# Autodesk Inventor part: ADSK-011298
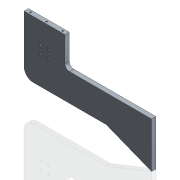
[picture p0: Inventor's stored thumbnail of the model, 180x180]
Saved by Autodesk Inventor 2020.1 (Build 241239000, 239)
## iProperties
Created: 1999-12
Part Number: ADSK-011298
Material: Pearson Aluminium
Document SubType Name: Modeling
Designer: sspink
Density: 2.71 g/cm^3
Appearance: Pearson-Aluminum
Mass: 1295.46 g
Surface Area: 939.34 cm^2
Volume: 478.029 cm^3
Control State: 0
Checked Out: False
Master: False
Shininess: 35.0
Length Units: 11269
Angle Units: 11279
Time Units: 11290
Mass Units: 11283
Length Display Precision: 3
Angle Display Precision: 2
Compacted: True
CUTLENGTH: 8.25 X 14.00 (116 SI)
MATERIAL DESC: SHEET,ALUM,0.50
MATERIAL_NUMBER: A101291
Dimensions: 356x210x12 mm
Mass: 1,295 kg
DocNumber: ADSK-011298.ipt
Folder: 01 - Themengebiete\Simplification\01 - Packaging machine\
VDS_Category: 3D Komponenten
Density: 2.71
Volumn: 499.8190191039328
Area: 951.0588557024685
PropertySet Name: Model Information
Author: sspink
Revision Number: -
Title: plate
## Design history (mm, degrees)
node "Solide1"
  node "Extrusion1" dims "d4" = 12, "d5" = 0
  node "Hole1" dims "d10" = 3.4, "d11" = 6.5, "d12" = 3.4, "d13" = 60 deg, "d14" = 19.05, "d15" = 118 deg, "d46" = 6
  node "Hole2" dims "d22" = 4.134, "d23" = 6.35, "d24" = 5.55625, "d25" = 60 deg, "d26" = 14.2, "d27" = 118 deg, "d48" = 10
sketch "Sketch1"
  geometry: L1 (-356, 210)-(-242, 210); L2 (-242, 210)-(-242, 139.5); L3 (-229.5, 127)-(0, 127); L4 (0, 127)-(0, 0); L5 (0, 0)-(-127, 50); L6 (-127, 50)-(-331, 50); L7 (-356, 75)-(-356, 210); L8 (-310, 151)-(-288, 151); L9 (-288, 151)-(-288, 129); L10 (-288, 129)-(-310, 129); L11 (-310, 129)-(-310, 151); A1 r 25 centre (-331, 75) between (-356, 75) and (-331, 50); A2 r 12.5 centre (-229.5, 139.5) between (-242, 139.5) and (-229.5, 127); 5 further points
  constraints: 22 end point, 5 perpendicular, 4 point on circle, 4 point on line, 4 tangent, 3 parallel, 2 centre point, 2 horizontal, 2 midpoint, 1 coincident, 1 vertical alignment
  dimensions: "d33" = 114 distance of L1.start L1.end; "d34" = 160 distance of point (-356, 50) L1.start; "d35" = 242 distance of point (-242, 127) L3.end; "d36" = 127 distance of L3.end L4.end; "d37" = 127 horizontal distance of L4.end L5.end; "d38" = 50 vertical distance of L4.end L5.end; "d39" = 25 radius of A1; "d40" = 12.5 radius of A2; "d43" = 22 distance of L8.start L8.end; "d44" = 22 distance of L8.end L9.end (= d43); "d45" = 59 distance from line of L1 L8.end
sketch "Sketch2"
  geometry: 4 further points
sketch "Sketch3"
  geometry: L1 (11.6, -6)-(101.6, -6); L2 (-0.4, 0)-(-0.4, -12) reference; L3 (-0.4, 0)-(113.6, 0) reference; 4 further points
  constraints: 3 midpoint, 2 end point, 1 coincident, 1 horizontal, 1 horizontal alignment, 1 vertical alignment
  dimensions: "d47" = 90 distance of L1.start L1.end
node "Corps solides"
node "Corps surfaciques"
